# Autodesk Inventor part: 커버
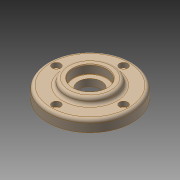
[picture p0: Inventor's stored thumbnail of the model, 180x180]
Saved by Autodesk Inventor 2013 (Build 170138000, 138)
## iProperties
Created: 2011-02
Part Number: 커버
Document SubType Name: Modeling
Designer: pww
Density: 1 g/cm^3
Material: 알루미늄 6061
Author: pww
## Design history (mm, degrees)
sketch "스케치1"
  geometry: C1 r 40 at (0, 0) reference
extrude "돌출1" new body sketch "스케치1" distance "d2" = 11; taper "d3" = 0 deg
sketch "스케치2"
  geometry: C1 r 23 at (0, 0); 1 further point
  constraints: 1 centre point, 1 coincident
  dimensions: "d4" = 46 diameter of C1
extrude "돌출2" join sketch "스케치2" distance "d5" = 6; taper "d6" = 0 deg
sketch "스케치3"
  geometry: C1 r 23.5 at (0, 0); 1 further point
  constraints: 1 centre point, 1 coincident
  dimensions: "d7" = 47 diameter of C1
extrude "돌출3" join sketch "스케치3" distance "d8" = 3; taper "d9" = 0 deg
hole "구멍1" diameter "d12" = 22; stored, may be unused: countersink angle "d16" = 90 deg, drill point angle "d18" = 118 deg; dims "d13" = 6, "d14" = 32, "d15" = 8.3, "d17" = 8, "d49" = 10, "d50" = 10
hole "구멍2" diameter "d21" = 40; stored, may be unused: countersink angle "d25" = 90 deg, drill point angle "d27" = 0 deg; dims "d22" = 6, "d23" = 32, "d24" = 8, "d26" = 5, "d44" = 10, "d45" = 10
fillet "모깎기1" dims "d28" = 3, "d43" = 0.3
chamfer "모따기1" distance "d29" = 0.8; stored, may be unused: second distance "d30" = 2, angle "d31" = 30 deg
sketch "스케치4"
  geometry: C1 r 1.621 at (0, -32) reference; 2 further points
  constraints: 1 coincident, 1 vertical alignment
hole "구멍3" sketch "스케치4" at (0, -32) diameter "d33" = 4.5; stored, may be unused: countersink angle "d37" = 90 deg, drill point angle "d39" = 118 deg; dims "d34" = 6, "d35" = 8, "d36" = 4.6, "d38" = 5
chamfer "모따기2" distance "d46" = 1; stored, may be unused: second distance "d47" = 2, angle "d48" = 45 deg
node "솔리드1"
pattern_circular "원형 패턴1" dims angle "d41" = 360 deg
node "참조1"
node "참조2"
